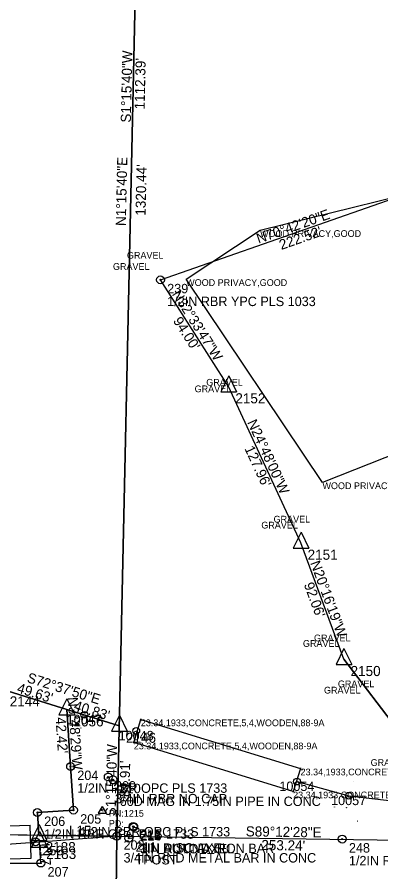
# Model space of a CAD drawing. Extents: x 1431802 to 1457777, y 1852108 to 1876350.
# Drawn here: x 1443655 to 1443925, y 1854914 to 1855549 of the extents above; entities that cross this region are included whole.
import ezdxf

# ---------------------------------------------------------------- set-up
doc = ezdxf.new("R2010")
doc.units = 0
for name, color, linetype in [('Default', 7, 'Continuous'), ('S_BRIDGE', 7, 'Continuous'), ('S_BRIDGE_ANNOT', 7, 'Continuous'), ('S_BUILDING', 7, 'Continuous'), ('S_CAL_CORNER', 7, 'Continuous'), ('S_CAL_CORNER_ANNOT', 7, 'Continuous'), ('S_DRIVEWAY_ANNOT', 7, 'Continuous'), ('S_EXISTING_ALIGNMENT', 7, 'Continuous'), ('S_EXISTING_ALIGNMENT_ANNOT', 7, 'Continuous'), ('S_FENCE', 7, 'Continuous'), ('S_FENCE_ANNOT', 7, 'Continuous'), ('S_IRON_PIN', 7, 'Continuous'), ('S_IRON_PIN_ANNOT', 7, 'Continuous'), ('S_MSC_PT_SYM', 7, 'Continuous'), ('S_PROPERTY', 7, 'Continuous'), ('S_PROPERTY_ANNOT', 7, 'Continuous'), ('S_QSECTION', 7, 'Continuous'), ('S_RDW_PT_SYM', 7, 'Continuous'), ('S_SECONDARY_CTL', 7, 'Continuous'), ('S_SECONDARY_CTL_ANNOT', 7, 'Continuous'), ('S_SECTION', 7, 'Continuous'), ('S_SECTION_ANNOT', 7, 'Continuous'), ('S_STR_PT_SYM', 7, 'Continuous')]:
    doc.layers.add(name, color=color, linetype=linetype)

msp = doc.modelspace()

# ---------------------------------------------------------------- linework, layer by layer
at = {"layer": 'Default'}
for points in [[(1443700.08, 1854944.94), (1443700.08, 1854944.99), (1443700.08, 1854944.94), (1443700.03, 1854944.94), (1443700.08, 1854944.94), (1443700.08, 1854944.89), (1443700.08, 1854944.94), (1443700.13, 1854944.94)], [(1443675.73, 1854928.96), (1443675.78, 1854928.96), (1443675.73, 1854928.96), (1443675.73, 1854929.01), (1443675.73, 1854928.96), (1443675.68, 1854928.96), (1443675.73, 1854928.96), (1443675.73, 1854928.91)]]:
    msp.add_lwpolyline(points, dxfattribs=at)
at = {"layer": 'S_BRIDGE'}
for p, q in [((1443741.54, 1855010.4), (1443746.75, 1855027.58)), ((1443746.75, 1855027.58), (1443865.37, 1854991.09)), ((1443859.85, 1854974.01), (1443741.54, 1855010.4)), ((1443865.37, 1854991.09), (1443859.85, 1854974.01))]:
    msp.add_line(p, q, dxfattribs=at)
at = {"layer": 'S_BUILDING'}
for p, q in [((1443664.71, 1854948.82), (1443640.45, 1854948.13)), ((1443665.32, 1854924.65), (1443664.71, 1854948.82)), ((1443641.13, 1854923.94), (1443665.32, 1854924.65))]:
    msp.add_line(p, q, dxfattribs=at)
at = {"layer": 'S_CAL_CORNER'}
for p, q in [((1443812.04, 1855282.8), (1443806.16, 1855270.98)), ((1443812.04, 1855282.8), (1443817.85, 1855270.98)), ((1443806.16, 1855270.98), (1443817.85, 1855270.98)), ((1443865.71, 1855166.64), (1443859.83, 1855154.83)), ((1443865.71, 1855166.64), (1443871.52, 1855154.83)), ((1443859.83, 1855154.83), (1443871.52, 1855154.83)), ((1443897.61, 1855080.29), (1443891.73, 1855068.47)), ((1443897.61, 1855080.29), (1443903.42, 1855068.47)), ((1443891.73, 1855068.47), (1443903.42, 1855068.47)), ((1443691.88, 1855042.91), (1443686, 1855031.1)), ((1443691.88, 1855042.91), (1443686, 1855031.1)), ((1443691.88, 1855042.91), (1443686, 1855031.1)), ((1443691.88, 1855042.91), (1443697.69, 1855031.1)), ((1443691.88, 1855042.91), (1443697.69, 1855031.1)), ((1443691.88, 1855042.91), (1443697.69, 1855031.1)), ((1443686, 1855031.1), (1443697.69, 1855031.1)), ((1443686, 1855031.1), (1443697.69, 1855031.1)), ((1443686, 1855031.1), (1443697.69, 1855031.1)), ((1443730.84, 1855030.73), (1443724.97, 1855018.91)), ((1443730.84, 1855030.73), (1443724.97, 1855018.91)), ((1443730.84, 1855030.73), (1443736.66, 1855018.91)), ((1443730.84, 1855030.73), (1443736.66, 1855018.91)), ((1443724.97, 1855018.91), (1443736.66, 1855018.91)), ((1443724.97, 1855018.91), (1443736.66, 1855018.91)), ((1443671.22, 1854949.51), (1443665.34, 1854937.69)), ((1443671.22, 1854949.51), (1443665.34, 1854937.69)), ((1443671.22, 1854949.51), (1443665.34, 1854937.69)), ((1443671.22, 1854949.51), (1443665.34, 1854937.69)), ((1443671.22, 1854949.51), (1443677.03, 1854937.69)), ((1443671.22, 1854949.51), (1443677.03, 1854937.69)), ((1443671.22, 1854949.51), (1443677.03, 1854937.69)), ((1443671.22, 1854949.51), (1443677.03, 1854937.69)), ((1443671.56, 1854944.47), (1443665.68, 1854932.65)), ((1443671.56, 1854944.47), (1443677.37, 1854932.65)), ((1443665.34, 1854937.69), (1443677.03, 1854937.69)), ((1443665.34, 1854937.69), (1443677.03, 1854937.69)), ((1443665.34, 1854937.69), (1443677.03, 1854937.69)), ((1443665.34, 1854937.69), (1443677.03, 1854937.69)), ((1443665.68, 1854932.65), (1443677.37, 1854932.65))]:
    msp.add_line(p, q, dxfattribs=at)
at = {"layer": 'S_EXISTING_ALIGNMENT'}
for p, q in [((1443862.74, 1854981.46), (1443901.18, 1854970.96)), ((1443901.18, 1854970.96), (1443941.5, 1854966.08))]:
    msp.add_line(p, q, dxfattribs=at)
for centre in [(1443704.8, 1855031.03), (1443743.39, 1855019.1), (1443862.74, 1854981.46), (1443901.18, 1854970.96)]:
    msp.add_circle(centre, 2.5, dxfattribs=at)
at = {"layer": 'S_FENCE'}
for p, q in [((1443835.31, 1855390.91), (1443975.13, 1855425.51)), ((1443780.43, 1855354.51), (1443835.31, 1855390.91)), ((1443881.63, 1855203.62), (1443780.43, 1855354.51)), ((1444015.05, 1855256.61), (1443881.63, 1855203.62))]:
    msp.add_line(p, q, dxfattribs=at)
at = {"layer": 'S_IRON_PIN'}
for centre, radius in [((1443761.35, 1855354.04), 2.91), ((1443761.35, 1855354.04), 0.411), ((1443761.35, 1855354.04), 0.262), ((1443761.35, 1855354.04), 0.212), ((1443761.35, 1855354.04), 0.145), ((1443761.35, 1855354.04), 0.0822), ((1443761.35, 1855354.04), 0.0581), ((1443694.61, 1854992.61), 2.91), ((1443694.61, 1854992.61), 0.411), ((1443694.61, 1854992.61), 0.262), ((1443694.61, 1854992.61), 0.212), ((1443694.61, 1854992.61), 0.145), ((1443694.61, 1854992.61), 0.0822), ((1443694.61, 1854992.61), 0.0581), ((1443722.59, 1854984.81), 2.91), ((1443722.59, 1854984.81), 0.411), ((1443722.59, 1854984.81), 0.262), ((1443722.59, 1854984.81), 0.212), ((1443722.59, 1854984.81), 0.145), ((1443722.59, 1854984.81), 0.0822), ((1443722.59, 1854984.81), 0.0581), ((1443726.11, 1854982.81), 2.91), ((1443726.11, 1854982.81), 0.411), ((1443726.11, 1854982.81), 0.262), ((1443726.11, 1854982.81), 0.212), ((1443726.11, 1854982.81), 0.145), ((1443726.11, 1854982.81), 0.0822), ((1443726.11, 1854982.81), 0.0581), ((1443669.99, 1854958.5), 2.91), ((1443696.76, 1854960.21), 2.91), ((1443696.76, 1854960.21), 0.411), ((1443696.76, 1854960.21), 0.262), ((1443696.76, 1854960.21), 0.212), ((1443669.99, 1854958.5), 0.411), ((1443669.99, 1854958.5), 0.262), ((1443669.99, 1854958.5), 0.212), ((1443669.99, 1854958.5), 0.145), ((1443669.99, 1854958.5), 0.0822), ((1443669.99, 1854958.5), 0.0581), ((1443696.76, 1854960.21), 0.145), ((1443696.76, 1854960.21), 0.0822), ((1443696.76, 1854960.21), 0.0581), ((1443741.09, 1854948.18), 2.91), ((1443741.36, 1854947.63), 2.91), ((1443741.51, 1854947.81), 2.91), ((1443741.09, 1854948.18), 0.411), ((1443741.09, 1854948.18), 0.262), ((1443741.09, 1854948.18), 0.212), ((1443741.09, 1854948.18), 0.145), ((1443741.36, 1854947.63), 0.411), ((1443741.09, 1854948.18), 0.0822), ((1443741.09, 1854948.18), 0.0581), ((1443741.51, 1854947.81), 0.411), ((1443741.36, 1854947.63), 0.262), ((1443741.36, 1854947.63), 0.212), ((1443741.36, 1854947.63), 0.145), ((1443741.51, 1854947.81), 0.262), ((1443741.36, 1854947.63), 0.0822), ((1443741.51, 1854947.81), 0.212), ((1443741.51, 1854947.81), 0.145), ((1443741.51, 1854947.81), 0.0822), ((1443741.51, 1854947.81), 0.0581), ((1443728.95, 1854940.85), 2.91), ((1443737.85, 1854939.41), 2.91), ((1443741.36, 1854947.63), 0.0581), ((1443896.29, 1854938.74), 2.91), ((1443668.64, 1854936.71), 2.91), ((1443668.64, 1854936.71), 0.411), ((1443668.64, 1854936.71), 0.262), ((1443668.64, 1854936.71), 0.212), ((1443668.64, 1854936.71), 0.145), ((1443668.64, 1854936.71), 0.0822), ((1443668.64, 1854936.71), 0.0581), ((1443728.95, 1854940.85), 0.411), ((1443728.95, 1854940.85), 0.262), ((1443728.95, 1854940.85), 0.212), ((1443728.95, 1854940.85), 0.145), ((1443728.95, 1854940.85), 0.0822), ((1443728.95, 1854940.85), 0.0581), ((1443737.85, 1854939.41), 0.411), ((1443737.85, 1854939.41), 0.262), ((1443737.85, 1854939.41), 0.212), ((1443737.85, 1854939.41), 0.145), ((1443737.85, 1854939.41), 0.0822), ((1443737.85, 1854939.41), 0.0581), ((1443896.29, 1854938.74), 0.411), ((1443896.29, 1854938.74), 0.262), ((1443896.29, 1854938.74), 0.212), ((1443896.29, 1854938.74), 0.145), ((1443896.29, 1854938.74), 0.0822), ((1443896.29, 1854938.74), 0.0581), ((1443672.51, 1854920.93), 2.91), ((1443672.51, 1854920.93), 0.411), ((1443672.51, 1854920.93), 0.262), ((1443672.51, 1854920.93), 0.212), ((1443672.51, 1854920.93), 0.145), ((1443672.51, 1854920.93), 0.0822), ((1443672.51, 1854920.93), 0.0581)]:
    msp.add_circle(centre, radius, dxfattribs=at)
at = {"layer": 'S_MSC_PT_SYM'}
for points in [[(1443835.31, 1855390.91), (1443835.31, 1855390.96), (1443835.31, 1855390.91), (1443835.26, 1855390.91), (1443835.31, 1855390.91), (1443835.31, 1855390.86), (1443835.31, 1855390.91), (1443835.36, 1855390.91)], [(1443780.43, 1855354.51), (1443780.43, 1855354.56), (1443780.43, 1855354.51), (1443780.38, 1855354.51), (1443780.43, 1855354.51), (1443780.43, 1855354.46), (1443780.43, 1855354.51), (1443780.48, 1855354.51)], [(1443881.63, 1855203.62), (1443881.63, 1855203.67), (1443881.63, 1855203.62), (1443881.58, 1855203.62), (1443881.63, 1855203.62), (1443881.63, 1855203.57), (1443881.63, 1855203.62), (1443881.68, 1855203.62)]]:
    msp.add_lwpolyline(points, dxfattribs=at)
at = {"layer": 'S_PROPERTY'}
for p, q in [((1443753.43, 1856052.97), (1443728.95, 1854940.85)), ((1443753.43, 1856052.97), (1443730.75, 1855022.75)), ((1443761.35, 1855354.04), (1443971.38, 1855427.57)), ((1443811.95, 1855274.82), (1443761.35, 1855354.04)), ((1443865.62, 1855158.66), (1443811.95, 1855274.82)), ((1443897.52, 1855072.31), (1443865.62, 1855158.66)), ((1443991.73, 1854948.61), (1443897.52, 1855072.31)), ((1443897.52, 1855072.31), (1443991.73, 1854948.61)), ((1443730.75, 1855022.75), (1443644.42, 1855049.75)), ((1443644.42, 1855049.75), (1443691.79, 1855034.93)), ((1443644.42, 1855049.75), (1443691.79, 1855034.93)), ((1443691.79, 1855034.93), (1443694.61, 1854992.61)), ((1443694.61, 1854992.61), (1443691.79, 1855034.93)), ((1443691.79, 1855034.93), (1443730.75, 1855022.75)), ((1443691.79, 1855034.93), (1443730.75, 1855022.75)), ((1443694.61, 1854992.61), (1443691.79, 1855034.93)), ((1443730.75, 1855022.75), (1443728.95, 1854940.85)), ((1443694.61, 1854992.61), (1443696.76, 1854960.21)), ((1443696.76, 1854960.21), (1443694.61, 1854992.61)), ((1443696.76, 1854960.21), (1443669.99, 1854958.5)), ((1443669.99, 1854958.5), (1443696.76, 1854960.21)), ((1443669.99, 1854958.5), (1443671.13, 1854941.53)), ((1443671.13, 1854941.53), (1443669.99, 1854958.5)), ((1443671.13, 1854941.53), (1443470.73, 1854943.86)), ((1443671.13, 1854941.53), (1443728.95, 1854940.85)), ((1443728.95, 1854940.85), (1443671.13, 1854941.53)), ((1443671.47, 1854936.49), (1443469.08, 1854921.13)), ((1443728.95, 1854940.85), (1443671.47, 1854936.49)), ((1443672.51, 1854920.93), (1443671.47, 1854936.49)), ((1443728.95, 1854940.85), (1443727.41, 1854821.5)), ((1443728.95, 1854940.85), (1443982.17, 1854937.35)), ((1443469.08, 1854921.13), (1443672.51, 1854920.93))]:
    msp.add_line(p, q, dxfattribs=at)
at = {"layer": 'S_QSECTION'}
msp.add_line((1443728.95, 1854940.85), (1443470.73, 1854943.86), dxfattribs=at)
at = {"layer": 'S_RDW_PT_SYM'}
for points in [[(1443749.72, 1855374.78), (1443749.72, 1855374.83), (1443749.72, 1855374.78), (1443749.67, 1855374.78), (1443749.72, 1855374.78), (1443749.72, 1855374.73), (1443749.72, 1855374.78), (1443749.77, 1855374.78)], [(1443739.33, 1855366.46), (1443739.33, 1855366.51), (1443739.33, 1855366.46), (1443739.28, 1855366.46), (1443739.33, 1855366.46), (1443739.33, 1855366.41), (1443739.33, 1855366.46), (1443739.38, 1855366.46)], [(1443808.62, 1855280.46), (1443808.62, 1855280.51), (1443808.62, 1855280.46), (1443808.57, 1855280.46), (1443808.62, 1855280.46), (1443808.62, 1855280.41), (1443808.62, 1855280.46), (1443808.67, 1855280.46)], [(1443799.97, 1855275.59), (1443799.97, 1855275.64), (1443799.97, 1855275.59), (1443799.92, 1855275.59), (1443799.97, 1855275.59), (1443799.97, 1855275.54), (1443799.97, 1855275.59), (1443800.02, 1855275.59)], [(1443858.61, 1855178.81), (1443858.61, 1855178.86), (1443858.61, 1855178.81), (1443858.56, 1855178.81), (1443858.61, 1855178.81), (1443858.61, 1855178.76), (1443858.61, 1855178.81), (1443858.66, 1855178.81)], [(1443849.51, 1855174.38), (1443849.51, 1855174.43), (1443849.51, 1855174.38), (1443849.46, 1855174.38), (1443849.51, 1855174.38), (1443849.51, 1855174.33), (1443849.51, 1855174.38), (1443849.56, 1855174.38)], [(1443888.62, 1855090.61), (1443888.62, 1855090.66), (1443888.62, 1855090.61), (1443888.57, 1855090.61), (1443888.62, 1855090.61), (1443888.62, 1855090.56), (1443888.62, 1855090.61), (1443888.67, 1855090.61)], [(1443880.4, 1855086.51), (1443880.4, 1855086.55), (1443880.4, 1855086.51), (1443880.35, 1855086.51), (1443880.4, 1855086.51), (1443880.4, 1855086.45), (1443880.4, 1855086.51), (1443880.45, 1855086.51)], [(1443906.36, 1855056.51), (1443906.36, 1855056.56), (1443906.36, 1855056.51), (1443906.31, 1855056.51), (1443906.36, 1855056.51), (1443906.36, 1855056.46), (1443906.36, 1855056.51), (1443906.41, 1855056.51)], [(1443896.05, 1855051.84), (1443896.05, 1855051.89), (1443896.05, 1855051.84), (1443896, 1855051.84), (1443896.05, 1855051.84), (1443896.05, 1855051.79), (1443896.05, 1855051.84), (1443896.1, 1855051.84)], [(1443707.4, 1855040.45), (1443707.4, 1855040.5), (1443707.4, 1855040.45), (1443707.35, 1855040.45), (1443707.4, 1855040.45), (1443707.4, 1855040.4), (1443707.4, 1855040.45), (1443707.45, 1855040.45)], [(1443745.74, 1855027.48), (1443745.74, 1855027.53), (1443745.74, 1855027.48), (1443745.69, 1855027.48), (1443745.74, 1855027.48), (1443745.74, 1855027.43), (1443745.74, 1855027.48), (1443745.79, 1855027.48)], [(1443702.24, 1855021.28), (1443702.24, 1855021.33), (1443702.24, 1855021.28), (1443702.19, 1855021.28), (1443702.24, 1855021.28), (1443702.24, 1855021.23), (1443702.24, 1855021.28), (1443702.29, 1855021.28)], [(1443741.17, 1855010.73), (1443741.17, 1855010.78), (1443741.17, 1855010.73), (1443741.12, 1855010.73), (1443741.17, 1855010.73), (1443741.17, 1855010.68), (1443741.17, 1855010.73), (1443741.22, 1855010.73)], [(1443866.73, 1854990.53), (1443866.73, 1854990.58), (1443866.73, 1854990.53), (1443866.68, 1854990.53), (1443866.73, 1854990.53), (1443866.73, 1854990.48), (1443866.73, 1854990.53), (1443866.78, 1854990.53)], [(1443904.49, 1854981.29), (1443904.49, 1854981.34), (1443904.49, 1854981.29), (1443904.44, 1854981.29), (1443904.49, 1854981.29), (1443904.49, 1854981.24), (1443904.49, 1854981.29), (1443904.54, 1854981.29)], [(1443860.67, 1854974.05), (1443860.67, 1854974.1), (1443860.67, 1854974.05), (1443860.62, 1854974.05), (1443860.67, 1854974.05), (1443860.67, 1854974), (1443860.67, 1854974.05), (1443860.72, 1854974.05)], [(1443890.53, 1854962.62), (1443890.53, 1854962.67), (1443890.53, 1854962.62), (1443890.48, 1854962.62), (1443890.53, 1854962.62), (1443890.53, 1854962.57), (1443890.53, 1854962.62), (1443890.58, 1854962.62)], [(1443899.6, 1854962.11), (1443899.6, 1854962.16), (1443899.6, 1854962.11), (1443899.55, 1854962.11), (1443899.6, 1854962.11), (1443899.6, 1854962.06), (1443899.6, 1854962.11), (1443899.65, 1854962.11)], [(1443907.55, 1854952.02), (1443907.55, 1854952.07), (1443907.55, 1854952.02), (1443907.51, 1854952.02), (1443907.55, 1854952.02), (1443907.55, 1854951.97), (1443907.55, 1854952.02), (1443907.6, 1854952.02)]]:
    msp.add_lwpolyline(points, dxfattribs=at)
at = {"layer": 'S_SECONDARY_CTL'}
for p, q in [((1443717.99, 1854962.96), (1443714.98, 1854958)), ((1443717.99, 1854962.96), (1443720.94, 1854958)), ((1443714.98, 1854958), (1443720.94, 1854958))]:
    msp.add_line(p, q, dxfattribs=at)
for radius in [0.311, 0.183, 0.103]:
    msp.add_circle((1443717.99, 1854960.35), radius, dxfattribs=at)
at = {"layer": 'S_SECTION'}
for p, q in [((1443728.95, 1854940.85), (1443758.01, 1856260.98)), ((1443711.83, 1853613.38), (1443728.95, 1854940.85))]:
    msp.add_line(p, q, dxfattribs=at)
at = {"layer": 'S_STR_PT_SYM'}
for points in [[(1443746.75, 1855027.58), (1443746.75, 1855028.08), (1443746.75, 1855027.58), (1443746.25, 1855027.58), (1443746.75, 1855027.58), (1443746.75, 1855027.08), (1443746.75, 1855027.58), (1443747.25, 1855027.58)], [(1443741.54, 1855010.4), (1443741.54, 1855010.9), (1443741.54, 1855010.4), (1443741.04, 1855010.4), (1443741.54, 1855010.4), (1443741.54, 1855009.9), (1443741.54, 1855010.4), (1443742.04, 1855010.4)], [(1443865.37, 1854991.09), (1443865.37, 1854991.59), (1443865.37, 1854991.09), (1443864.87, 1854991.09), (1443865.37, 1854991.09), (1443865.37, 1854990.59), (1443865.37, 1854991.09), (1443865.87, 1854991.09)], [(1443859.85, 1854974.01), (1443859.85, 1854974.51), (1443859.85, 1854974.01), (1443859.35, 1854974.01), (1443859.85, 1854974.01), (1443859.85, 1854973.51), (1443859.85, 1854974.01), (1443860.35, 1854974.01)], [(1443664.71, 1854948.82), (1443664.71, 1854948.87), (1443664.71, 1854948.82), (1443664.66, 1854948.82), (1443664.71, 1854948.82), (1443664.71, 1854948.77), (1443664.71, 1854948.82), (1443664.76, 1854948.82)], [(1443665.32, 1854924.65), (1443665.32, 1854924.7), (1443665.32, 1854924.65), (1443665.27, 1854924.65), (1443665.32, 1854924.65), (1443665.32, 1854924.6), (1443665.32, 1854924.65), (1443665.37, 1854924.65)]]:
    msp.add_lwpolyline(points, dxfattribs=at)

# ---------------------------------------------------------------- texts
at = {"layer": 'S_BRIDGE_ANNOT'}
for p in [(1443746.75, 1855022.58), (1443741.54, 1855005.4), (1443865.37, 1854986.09), (1443859.85, 1854969.01)]:
    msp.add_text('23.34,1933,CONCRETE,5,4,WOODEN,88-9A', height=5, dxfattribs=at).set_placement(p)
at = {"layer": 'S_CAL_CORNER_ANNOT'}
for s, p in [('2152', (1443816.95, 1855262.32)), ('2151', (1443870.62, 1855146.16)), ('2150', (1443902.52, 1855059.81)), ('2144', (1443649.42, 1855037.25)), ('2056', (1443696.79, 1855022.43)), ('2146', (1443735.75, 1855010.25)), ('2188', (1443676.13, 1854929.03)), ('2183', (1443676.47, 1854923.99))]:
    msp.add_text(s, height=7.5, dxfattribs=at).set_placement(p)
at = {"layer": 'S_DRIVEWAY_ANNOT'}
for p in [(1443736.45, 1855369.78), (1443726.06, 1855361.46), (1443795.35, 1855275.46), (1443786.71, 1855270.59), (1443845.34, 1855173.81), (1443836.24, 1855169.38), (1443875.36, 1855085.61), (1443867.13, 1855081.51), (1443893.09, 1855051.51), (1443882.78, 1855046.84), (1443917.4, 1854993.09)]:
    msp.add_text('GRAVEL', height=5, dxfattribs=at).set_placement(p)
at = {"layer": 'S_EXISTING_ALIGNMENT_ANNOT'}
for s, p in [('10047', (1443691.68, 1855024.03)), ('10048', (1443730.27, 1855012.1)), ('10054', (1443849.63, 1854974.46)), ('10057', (1443888.06, 1854963.96))]:
    msp.add_text(s, height=7, dxfattribs=at).set_placement(p)
at = {"layer": 'S_FENCE_ANNOT'}
for p in [(1443835.31, 1855385.91), (1443780.43, 1855349.51), (1443881.63, 1855198.62)]:
    msp.add_text('WOOD PRIVACY,GOOD', height=5, dxfattribs=at).set_placement(p)
at = {"layer": 'S_IRON_PIN_ANNOT'}
for s, p in [('239', (1443766.35, 1855344.04)), ('1/2IN RBR YPC PLS 1033', (1443766.35, 1855334.54)), ('204', (1443699.61, 1854982.61)), ('1/2IN RBR OPC PLS 1733', (1443699.61, 1854973.11)), ('209', (1443727.59, 1854974.81)), ('210', (1443731.11, 1854972.81)), ('3/4IN RBR NO CAP', (1443727.59, 1854965.31)), ('60D MAG IN 1.75IN PIPE IN CONC', (1443731.11, 1854963.31)), ('206', (1443674.99, 1854948.5)), ('205', (1443701.76, 1854950.22)), ('1/2IN RBR OPC PLS 1733', (1443701.76, 1854940.72)), ('1/2IN RBR OPC PLS 1733', (1443674.99, 1854939)), ('212', (1443746.09, 1854938.18)), ('214', (1443746.36, 1854937.64)), ('213', (1443746.51, 1854937.81)), ('208', (1443733.95, 1854930.85)), ('211', (1443742.85, 1854929.42)), ('3IN AUTO AXEL', (1443746.36, 1854928.14)), ('1IN DISC AXEL', (1443746.09, 1854928.68)), ('1IN ROUND IRON BAR', (1443746.51, 1854928.31)), ('248', (1443901.29, 1854928.74)), ('253', (1443673.64, 1854926.71)), ('3/4IN RND METAL BAR IN CONC', (1443733.95, 1854921.35)), ('TPOST', (1443742.85, 1854919.92)), ('1/2IN RBR OPC PLS 1733', (1443901.29, 1854919.24)), ('207', (1443677.51, 1854910.93))]:
    msp.add_text(s, height=7, dxfattribs=at).set_placement(p)
at = {"layer": 'S_PROPERTY_ANNOT'}
for s, rotation, p in [('S1%%d15\'40"W', 88.73884, (1443739.36, 1855470.73)), ("1112.39'", 88.73884, (1443749.58, 1855480.48)), ('N70%%d42\'20"E', 19.29442, (1443834.18, 1855380.86)), ("222.52'", 19.29442, (1443851.09, 1855376.19)), ('N32%%d33\'47"W', 302.56303, (1443769.65, 1855343.38)), ("94.00'", 302.56303, (1443770.41, 1855323.61)), ('N24%%d48\'00"W', 294.79998, (1443825.6, 1855248.25)), ("127.96'", 294.79998, (1443823.58, 1855228.78)), ('N20%%d16\'19"W', 290.27192, (1443872.43, 1855143.84)), ("92.06'", 290.27192, (1443867.69, 1855127.8)), ('S72%%d37\'50"E', 342.63058, (1443661.65, 1855055.42)), ("49.63'", 342.63058, (1443654.23, 1855047.74)), ('N3%%d48\'29"W', 273.80809, (1443692.44, 1855043.96)), ("40.83'", 342.63058, (1443696.47, 1855034.68)), ("42.42'", 273.80809, (1443683.41, 1855029.04)), ('S1%%d15\'40"W', 88.73884, (1443728.02, 1854955.61)), ("81.91'", 88.73884, (1443738.34, 1854969.98)), ('L15', 359.33328, (1443693.31, 1854941.27)), ('S89%%d12\'28"E', 359.2077, (1443824.63, 1854940.78)), ('L17', 273.83108, (1443671.54, 1854935.43)), ("253.24'", 359.2077, (1443836.19, 1854930.62))]:
    msp.add_text(s, height=7.5, rotation=rotation, dxfattribs=at).set_placement(p)
at = {"layer": 'S_SECONDARY_CTL'}
msp.add_text('TV', height=1.5, dxfattribs=at).set_placement((1443716.79, 1854958.34))
at = {"layer": 'S_SECONDARY_CTL_ANNOT'}
for s, p in [('PN:1215', (1443722.99, 1854955.35)), ('PD:', (1443722.99, 1854947.85))]:
    msp.add_text(s, height=5, dxfattribs=at).set_placement(p)
at = {"layer": 'S_SECTION_ANNOT'}
for s, p in [('N1%%d15\'40"E', (1443735.63, 1855393.95)), ("1320.44'", (1443750.24, 1855401.61))]:
    msp.add_text(s, height=7.5, rotation=88.73884, dxfattribs=at).set_placement(p)

doc.saveas('drawing.dxf')
